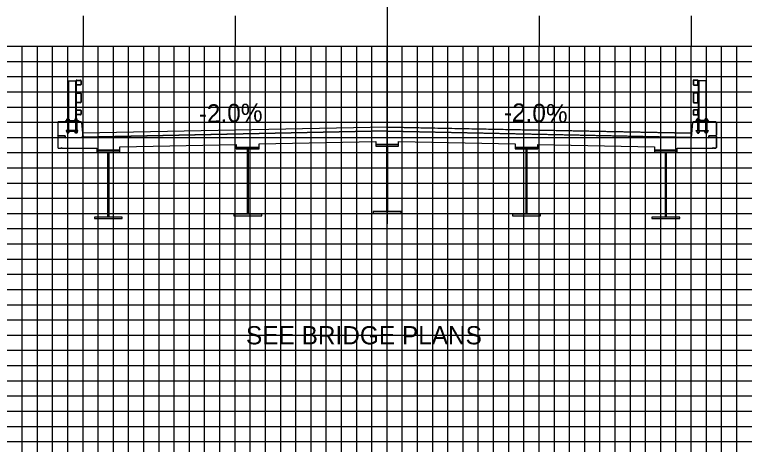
# Model space of a CAD drawing. Extents: x 1790124 to 1790467, y 442591 to 442811.
# Drawn here: x 1790265.2 to 1790313.2, y 442752.48 to 442780.74 of the extents above; entities that cross this region are included whole.
import ezdxf

# ---------------------------------------------------------------- set-up
doc = ezdxf.new("R2010")
doc.units = 0
for name, color, linetype in [('ANNOTATION', 7, 'Continuous'), ('BORDER', 7, 'Continuous'), ('D_Bridge_Framing', 7, 'Continuous'), ('D_Bridge_Railing', 7, 'Continuous'), ('D_Bridge_Superstructure', 7, 'Continuous'), ('DIMENSIONS', 7, 'Continuous'), ('MAJOR', 7, 'Continuous'), ('MINOR', 7, 'Continuous'), ('PATTERNING', 7, 'Continuous'), ('SHADING', 7, 'Continuous')]:
    doc.layers.add(name, color=color, linetype=linetype)

msp = doc.modelspace()

# ---------------------------------------------------------------- linework, layer by layer
at = {"layer": 'BORDER'}
for p, q in [((1790280.529, 442771.864), (1790280.529, 442770.826)), ((1790289.696, 442771.968), (1790289.696, 442770.93)), ((1790298.862, 442771.968), (1790298.862, 442770.93))]:
    msp.add_line(p, q, dxfattribs=at)
at = {"layer": 'D_Bridge_Framing'}
for points in [[(1790288.946, 442772.089), (1790290.446, 442772.089), (1790290.446, 442772.193), (1790288.946, 442772.193)], [(1790270.612, 442771.722), (1790272.112, 442771.722), (1790272.112, 442771.826), (1790270.612, 442771.826)], [(1790271.339, 442771.722), (1790271.386, 442771.722), (1790271.386, 442767.43), (1790271.339, 442767.43)], [(1790279.779, 442771.905), (1790281.279, 442771.905), (1790281.279, 442772.009), (1790279.779, 442772.009)], [(1790280.506, 442771.905), (1790280.553, 442771.905), (1790280.553, 442767.614), (1790280.506, 442767.614)], [(1790289.672, 442772.089), (1790289.719, 442772.089), (1790289.719, 442767.797), (1790289.672, 442767.797)], [(1790298.112, 442771.905), (1790299.612, 442771.905), (1790299.612, 442772.009), (1790298.112, 442772.009)], [(1790298.839, 442771.905), (1790298.886, 442771.905), (1790298.886, 442767.614), (1790298.839, 442767.614)], [(1790307.279, 442771.722), (1790308.779, 442771.722), (1790308.779, 442771.826), (1790307.279, 442771.826)], [(1790308.006, 442771.722), (1790308.053, 442771.722), (1790308.053, 442767.43), (1790308.006, 442767.43)], [(1790270.446, 442767.326), (1790272.279, 442767.326), (1790272.279, 442767.43), (1790270.446, 442767.43)], [(1790279.612, 442767.509), (1790281.446, 442767.509), (1790281.446, 442767.614), (1790279.612, 442767.614)], [(1790288.779, 442767.693), (1790290.612, 442767.693), (1790290.612, 442767.797), (1790288.779, 442767.797)], [(1790297.946, 442767.509), (1790299.779, 442767.509), (1790299.779, 442767.614), (1790297.946, 442767.614)], [(1790307.112, 442767.326), (1790308.946, 442767.326), (1790308.946, 442767.43), (1790307.112, 442767.43)]]:
    msp.add_lwpolyline(points, close=True, dxfattribs=at)
at = {"layer": 'D_Bridge_Railing'}
for p, q in [((1790268.706, 442776.395), (1790268.706, 442773.938)), ((1790268.706, 442776.395), (1790269.237, 442776.395)), ((1790268.743, 442776.395), (1790268.743, 442773.933)), ((1790269.201, 442776.395), (1790269.201, 442773.933)), ((1790269.237, 442776.145), (1790269.237, 442776.395)), ((1790269.237, 442776.395), (1790269.237, 442773.938)), ((1790269.258, 442776.145), (1790269.258, 442776.395)), ((1790269.279, 442776.437), (1790269.529, 442776.437)), ((1790269.279, 442776.416), (1790269.529, 442776.416)), ((1790269.529, 442776.124), (1790269.279, 442776.124)), ((1790269.529, 442776.104), (1790269.279, 442776.104)), ((1790269.55, 442776.395), (1790269.55, 442776.145)), ((1790269.571, 442776.395), (1790269.571, 442776.145)), ((1790309.821, 442776.395), (1790309.821, 442776.145)), ((1790309.842, 442776.395), (1790309.842, 442776.145)), ((1790310.113, 442776.437), (1790309.862, 442776.437)), ((1790310.113, 442776.416), (1790309.862, 442776.416)), ((1790309.862, 442776.124), (1790310.113, 442776.124)), ((1790309.862, 442776.104), (1790310.113, 442776.104)), ((1790310.133, 442776.145), (1790310.133, 442776.395)), ((1790310.154, 442776.145), (1790310.154, 442776.395)), ((1790310.154, 442776.395), (1790310.154, 442773.938)), ((1790310.685, 442776.395), (1790310.154, 442776.395)), ((1790310.191, 442776.395), (1790310.191, 442773.933)), ((1790310.649, 442776.395), (1790310.649, 442773.933)), ((1790310.685, 442776.395), (1790310.685, 442773.938)), ((1790269.237, 442774.989), (1790269.237, 442775.552)), ((1790269.263, 442774.989), (1790269.263, 442775.552)), ((1790269.289, 442775.604), (1790269.519, 442775.604)), ((1790269.289, 442775.578), (1790269.519, 442775.578)), ((1790269.545, 442775.552), (1790269.545, 442774.989)), ((1790269.571, 442775.552), (1790269.571, 442774.989)), ((1790309.821, 442775.552), (1790309.821, 442774.989)), ((1790309.847, 442775.552), (1790309.847, 442774.989)), ((1790310.102, 442775.604), (1790309.873, 442775.604)), ((1790310.102, 442775.578), (1790309.873, 442775.578)), ((1790310.128, 442774.989), (1790310.128, 442775.552)), ((1790310.154, 442774.989), (1790310.154, 442775.552)), ((1790269.519, 442774.963), (1790269.289, 442774.963)), ((1790269.519, 442774.937), (1790269.289, 442774.937)), ((1790309.873, 442774.963), (1790310.102, 442774.963)), ((1790309.873, 442774.937), (1790310.102, 442774.937)), ((1790269.237, 442774.187), (1790269.237, 442774.437)), ((1790269.258, 442774.187), (1790269.258, 442774.437)), ((1790269.279, 442774.479), (1790269.529, 442774.479)), ((1790269.279, 442774.458), (1790269.529, 442774.458)), ((1790269.529, 442774.166), (1790269.279, 442774.166)), ((1790269.529, 442774.145), (1790269.279, 442774.145)), ((1790269.55, 442774.437), (1790269.55, 442774.187)), ((1790269.571, 442774.437), (1790269.571, 442774.187)), ((1790309.821, 442774.437), (1790309.821, 442774.187)), ((1790309.842, 442774.437), (1790309.842, 442774.187)), ((1790310.113, 442774.479), (1790309.862, 442774.479)), ((1790310.113, 442774.458), (1790309.862, 442774.458)), ((1790309.862, 442774.166), (1790310.113, 442774.166)), ((1790309.862, 442774.145), (1790310.113, 442774.145)), ((1790310.133, 442774.187), (1790310.133, 442774.437)), ((1790310.154, 442774.187), (1790310.154, 442774.437)), ((1790268.665, 442773.928), (1790268.748, 442773.928)), ((1790268.665, 442773.866), (1790268.665, 442773.803)), ((1790268.665, 442773.687), (1790268.665, 442773.781)), ((1790268.706, 442773.938), (1790268.706, 442773.781)), ((1790268.747, 442773.866), (1790268.747, 442773.803)), ((1790268.748, 442773.687), (1790268.748, 442773.781)), ((1790269.279, 442773.928), (1790269.196, 442773.928)), ((1790269.196, 442773.866), (1790269.196, 442773.803)), ((1790269.196, 442773.687), (1790269.196, 442773.781)), ((1790269.238, 442773.938), (1790269.238, 442773.781)), ((1790269.279, 442773.866), (1790269.279, 442773.803)), ((1790269.279, 442773.687), (1790269.279, 442773.781)), ((1790310.112, 442773.928), (1790310.196, 442773.928)), ((1790310.112, 442773.687), (1790310.112, 442773.781)), ((1790310.113, 442773.866), (1790310.113, 442773.803)), ((1790310.154, 442773.938), (1790310.154, 442773.781)), ((1790310.195, 442773.866), (1790310.195, 442773.803)), ((1790310.196, 442773.687), (1790310.196, 442773.781)), ((1790310.727, 442773.928), (1790310.644, 442773.928)), ((1790310.644, 442773.866), (1790310.644, 442773.803)), ((1790310.644, 442773.687), (1790310.644, 442773.781)), ((1790310.685, 442773.938), (1790310.685, 442773.781)), ((1790310.726, 442773.866), (1790310.726, 442773.803)), ((1790310.727, 442773.687), (1790310.727, 442773.781)), ((1790268.665, 442773.117), (1790268.665, 442773.086)), ((1790268.748, 442773.117), (1790268.748, 442773.086)), ((1790269.196, 442773.117), (1790269.196, 442773.086)), ((1790269.279, 442773.117), (1790269.279, 442773.086)), ((1790310.112, 442773.117), (1790310.112, 442773.086)), ((1790310.196, 442773.117), (1790310.196, 442773.086)), ((1790310.644, 442773.117), (1790310.644, 442773.086)), ((1790310.727, 442773.117), (1790310.727, 442773.086))]:
    msp.add_line(p, q, dxfattribs=at)
for points in [[(1790268.555, 442773.781), (1790269.388, 442773.781), (1790269.388, 442773.697), (1790268.555, 442773.697)], [(1790268.555, 442773.697), (1790269.388, 442773.697), (1790269.388, 442773.687), (1790268.555, 442773.687)], [(1790268.619, 442773.781), (1790268.793, 442773.781), (1790268.793, 442773.794), (1790268.619, 442773.794)], [(1790268.624, 442773.866), (1790268.64, 442773.876), (1790268.772, 442773.876), (1790268.788, 442773.866), (1790268.788, 442773.803), (1790268.772, 442773.794), (1790268.64, 442773.794), (1790268.624, 442773.803)], [(1790269.324, 442773.781), (1790269.151, 442773.781), (1790269.151, 442773.794), (1790269.324, 442773.794)], [(1790269.32, 442773.866), (1790269.303, 442773.876), (1790269.171, 442773.876), (1790269.155, 442773.866), (1790269.155, 442773.803), (1790269.171, 442773.794), (1790269.303, 442773.794), (1790269.32, 442773.803)], [(1790310.836, 442773.781), (1790310.003, 442773.781), (1790310.003, 442773.697), (1790310.836, 442773.697)], [(1790310.836, 442773.697), (1790310.003, 442773.697), (1790310.003, 442773.687), (1790310.836, 442773.687)], [(1790310.067, 442773.781), (1790310.241, 442773.781), (1790310.241, 442773.794), (1790310.067, 442773.794)], [(1790310.072, 442773.866), (1790310.088, 442773.876), (1790310.22, 442773.876), (1790310.236, 442773.866), (1790310.236, 442773.803), (1790310.22, 442773.794), (1790310.088, 442773.794), (1790310.072, 442773.803)], [(1790310.772, 442773.781), (1790310.599, 442773.781), (1790310.599, 442773.794), (1790310.772, 442773.794)], [(1790310.768, 442773.866), (1790310.751, 442773.876), (1790310.619, 442773.876), (1790310.603, 442773.866), (1790310.603, 442773.803), (1790310.619, 442773.794), (1790310.751, 442773.794), (1790310.768, 442773.803)], [(1790269.362, 442773.117), (1790268.581, 442773.117), (1790268.581, 442773.086), (1790269.362, 442773.086)], [(1790310.029, 442773.117), (1790310.81, 442773.117), (1790310.81, 442773.086), (1790310.029, 442773.086)]]:
    msp.add_lwpolyline(points, close=True, dxfattribs=at)
for points in [[(1790268.665, 442773.876), (1790268.665, 442773.928), (1790268.675, 442773.938), (1790268.737, 442773.938), (1790268.748, 442773.928), (1790268.748, 442773.876)], [(1790268.665, 442773.687), (1790268.665, 442773.117)], [(1790268.748, 442773.687), (1790268.748, 442773.117)], [(1790269.279, 442773.876), (1790269.279, 442773.928), (1790269.269, 442773.938), (1790269.206, 442773.938), (1790269.196, 442773.928), (1790269.196, 442773.876)], [(1790269.196, 442773.687), (1790269.196, 442773.117)], [(1790269.279, 442773.687), (1790269.279, 442773.117)], [(1790310.112, 442773.876), (1790310.112, 442773.928), (1790310.123, 442773.938), (1790310.185, 442773.938), (1790310.196, 442773.928), (1790310.196, 442773.876)], [(1790310.112, 442773.687), (1790310.112, 442773.117)], [(1790310.196, 442773.687), (1790310.196, 442773.117)], [(1790310.727, 442773.876), (1790310.727, 442773.928), (1790310.717, 442773.938), (1790310.654, 442773.938), (1790310.644, 442773.928), (1790310.644, 442773.876)], [(1790310.644, 442773.687), (1790310.644, 442773.117)], [(1790310.727, 442773.687), (1790310.727, 442773.117)], [(1790268.793, 442773.086), (1790268.793, 442773.072), (1790268.619, 442773.072), (1790268.619, 442773.086)], [(1790268.64, 442773.072), (1790268.624, 442773.063), (1790268.624, 442773), (1790268.64, 442772.99), (1790268.772, 442772.99), (1790268.788, 442773), (1790268.788, 442773.063), (1790268.772, 442773.072)], [(1790268.665, 442772.99), (1790268.665, 442772.949), (1790268.675, 442772.938), (1790268.737, 442772.938), (1790268.748, 442772.949), (1790268.748, 442772.99)], [(1790269.151, 442773.086), (1790269.151, 442773.072), (1790269.324, 442773.072), (1790269.324, 442773.086)], [(1790269.303, 442773.072), (1790269.32, 442773.063), (1790269.32, 442773), (1790269.303, 442772.99), (1790269.171, 442772.99), (1790269.155, 442773), (1790269.155, 442773.063), (1790269.171, 442773.072)], [(1790269.279, 442772.99), (1790269.279, 442772.949), (1790269.269, 442772.938), (1790269.206, 442772.938), (1790269.196, 442772.949), (1790269.196, 442772.99)], [(1790310.241, 442773.086), (1790310.241, 442773.072), (1790310.067, 442773.072), (1790310.067, 442773.086)], [(1790310.088, 442773.072), (1790310.072, 442773.063), (1790310.072, 442773), (1790310.088, 442772.99), (1790310.22, 442772.99), (1790310.236, 442773), (1790310.236, 442773.063), (1790310.22, 442773.072)], [(1790310.112, 442772.99), (1790310.112, 442772.949), (1790310.123, 442772.938), (1790310.185, 442772.938), (1790310.196, 442772.949), (1790310.196, 442772.99)], [(1790310.599, 442773.086), (1790310.599, 442773.072), (1790310.772, 442773.072), (1790310.772, 442773.086)], [(1790310.751, 442773.072), (1790310.768, 442773.063), (1790310.768, 442773), (1790310.751, 442772.99), (1790310.619, 442772.99), (1790310.603, 442773), (1790310.603, 442773.063), (1790310.619, 442773.072)], [(1790310.727, 442772.99), (1790310.727, 442772.949), (1790310.717, 442772.938), (1790310.654, 442772.938), (1790310.644, 442772.949), (1790310.644, 442772.99)]]:
    msp.add_lwpolyline(points, dxfattribs=at)
for centre, radius, start, end in [((1790269.279, 442776.395), 0.0415, 90, 180), ((1790269.279, 442776.145), 0.0415, 180, 270), ((1790269.279, 442776.395), 0.0206, 90, 180), ((1790269.279, 442776.145), 0.0206, 180, 270), ((1790269.529, 442776.395), 0.0415, 0, 90), ((1790269.529, 442776.395), 0.0206, 0, 90), ((1790269.529, 442776.145), 0.0415, 270, 0), ((1790269.529, 442776.145), 0.0206, 270, 0), ((1790309.862, 442776.395), 0.0415, 90, 180), ((1790309.862, 442776.145), 0.0415, 180, 270), ((1790309.862, 442776.395), 0.0206, 90, 180), ((1790309.862, 442776.145), 0.0206, 180, 270), ((1790310.113, 442776.395), 0.0415, 0, 90), ((1790310.113, 442776.395), 0.0206, 0, 90), ((1790310.113, 442776.145), 0.0415, 270, 0), ((1790310.113, 442776.145), 0.0206, 270, 0), ((1790269.289, 442775.552), 0.0518, 90, 180), ((1790269.289, 442775.552), 0.0257, 90, 180), ((1790269.519, 442775.552), 0.0518, 360, 90), ((1790269.519, 442775.552), 0.0257, 360, 90), ((1790309.873, 442775.552), 0.0518, 90, 180), ((1790309.873, 442775.552), 0.0257, 90, 180), ((1790310.102, 442775.552), 0.0518, 0, 90), ((1790310.102, 442775.552), 0.0257, 0, 90), ((1790269.289, 442774.989), 0.0518, 180, 270), ((1790269.289, 442774.989), 0.0257, 180, 270), ((1790269.519, 442774.989), 0.0518, 270, 0), ((1790269.519, 442774.989), 0.0257, 270, 0), ((1790309.873, 442774.989), 0.0518, 180, 270), ((1790309.873, 442774.989), 0.0257, 180, 270), ((1790310.102, 442774.989), 0.0518, 270, 0), ((1790310.102, 442774.989), 0.0257, 270, 360), ((1790269.279, 442774.437), 0.0415, 90, 180), ((1790269.279, 442774.187), 0.0415, 180, 270), ((1790269.279, 442774.437), 0.0206, 90, 180), ((1790269.279, 442774.187), 0.0206, 180, 270), ((1790269.529, 442774.437), 0.0415, 0, 90), ((1790269.529, 442774.437), 0.0206, 0, 90), ((1790269.529, 442774.187), 0.0415, 270, 0), ((1790269.529, 442774.187), 0.0206, 270, 0), ((1790309.862, 442774.437), 0.0415, 90, 180), ((1790309.862, 442774.187), 0.0415, 180, 270), ((1790309.862, 442774.437), 0.0206, 90, 180), ((1790309.862, 442774.187), 0.0206, 180, 270), ((1790310.113, 442774.437), 0.0415, 0, 90), ((1790310.113, 442774.437), 0.0206, 0, 90), ((1790310.113, 442774.187), 0.0415, 270, 0), ((1790310.113, 442774.187), 0.0206, 270, 0), ((1790268.645, 442773.837), 0.036, 55.4339, 120), ((1790268.645, 442773.833), 0.036, 240, 304.5661), ((1790268.706, 442773.737), 0.136, 72.412, 107.588), ((1790268.706, 442773.933), 0.136, 252.412, 287.588), ((1790268.768, 442773.837), 0.036, 60, 124.5661), ((1790268.768, 442773.833), 0.036, 235.4339, 300), ((1790269.176, 442773.837), 0.036, 55.4339, 120), ((1790269.176, 442773.833), 0.036, 240, 304.5661), ((1790269.237, 442773.737), 0.136, 72.412, 107.588), ((1790269.237, 442773.933), 0.136, 252.412, 287.588), ((1790269.299, 442773.837), 0.036, 60, 124.5661), ((1790269.299, 442773.833), 0.036, 235.4339, 300), ((1790310.093, 442773.837), 0.036, 55.4339, 120), ((1790310.093, 442773.833), 0.036, 240, 304.5661), ((1790310.154, 442773.737), 0.136, 72.412, 107.588), ((1790310.154, 442773.933), 0.136, 252.412, 287.588), ((1790310.216, 442773.837), 0.036, 60, 124.5661), ((1790310.216, 442773.833), 0.036, 235.4339, 300), ((1790310.624, 442773.837), 0.036, 55.4339, 120), ((1790310.624, 442773.833), 0.036, 240, 304.5661), ((1790310.685, 442773.737), 0.136, 72.412, 107.588), ((1790310.685, 442773.933), 0.136, 252.412, 287.588), ((1790310.747, 442773.837), 0.036, 60, 124.5661), ((1790310.747, 442773.833), 0.036, 235.4339, 300)]:
    msp.add_arc(centre, radius, start, end, dxfattribs=at)
at = {"layer": 'D_Bridge_Superstructure'}
for p, q in [((1790268.029, 442773.645), (1790268.071, 442773.687)), ((1790268.029, 442773.645), (1790268.029, 442772.811)), ((1790269.571, 442773.687), (1790268.071, 442773.687)), ((1790269.616, 442773.645), (1790269.571, 442773.687)), ((1790269.616, 442773.645), (1790269.696, 442772.668)), ((1790309.776, 442773.645), (1790309.696, 442772.668)), ((1790309.776, 442773.645), (1790309.821, 442773.687)), ((1790309.821, 442773.687), (1790311.321, 442773.687)), ((1790311.362, 442773.645), (1790311.321, 442773.687)), ((1790311.362, 442773.645), (1790311.362, 442772.811)), ((1790289.696, 442773.339), (1790269.674, 442772.938)), ((1790289.696, 442773.339), (1790309.718, 442772.938)), ((1790268.071, 442772.769), (1790268.029, 442772.811)), ((1790268.529, 442772.769), (1790268.071, 442772.769)), ((1790268.529, 442772.769), (1790268.071, 442772.769)), ((1790289.696, 442773.068), (1790268.529, 442772.644)), ((1790268.529, 442772.769), (1790268.529, 442772.644)), ((1790268.529, 442772.644), (1790268.529, 442772.769)), ((1790289.696, 442773.089), (1790269.694, 442772.689)), ((1790289.696, 442773.089), (1790309.697, 442772.689)), ((1790289.696, 442773.068), (1790310.862, 442772.644)), ((1790309.696, 442772.668), (1790289.696, 442773.068)), ((1790310.862, 442772.644), (1790309.696, 442772.668)), ((1790310.862, 442772.769), (1790310.862, 442772.644)), ((1790310.862, 442772.769), (1790311.321, 442772.769)), ((1790311.321, 442772.769), (1790310.862, 442772.769)), ((1790310.862, 442772.769), (1790310.862, 442772.644)), ((1790311.321, 442772.769), (1790311.362, 442772.811)), ((1790288.946, 442772.193), (1790290.446, 442772.193)), ((1790268.237, 442771.968), (1790268.279, 442772.009)), ((1790268.279, 442772.009), (1790268.279, 442771.968)), ((1790270.612, 442771.826), (1790272.112, 442771.826)), ((1790279.779, 442772.009), (1790281.279, 442772.009)), ((1790298.112, 442772.009), (1790299.612, 442772.009)), ((1790307.279, 442771.826), (1790308.779, 442771.826)), ((1790311.112, 442771.968), (1790311.112, 442772.009)), ((1790311.112, 442772.009), (1790311.154, 442771.968))]:
    msp.add_line(p, q, dxfattribs=at)
for points in [[(1790268.071, 442772.769), (1790268.029, 442772.728), (1790268.029, 442772.009), (1790268.071, 442771.968), (1790268.237, 442771.968)], [(1790268.071, 442772.769), (1790268.029, 442772.728), (1790268.029, 442772.009), (1790268.071, 442771.968), (1790268.237, 442771.968)], [(1790289.696, 442773.068), (1790269.696, 442772.668), (1790268.529, 442772.644)], [(1790311.321, 442772.769), (1790311.362, 442772.728), (1790311.362, 442772.009), (1790311.321, 442771.968), (1790311.154, 442771.968)], [(1790311.154, 442771.968), (1790311.321, 442771.968), (1790311.362, 442772.009), (1790311.362, 442772.728), (1790311.321, 442772.769)], [(1790272.112, 442771.826), (1790272.112, 442772.049), (1790279.779, 442772.203), (1790279.779, 442772.009)], [(1790281.279, 442772.009), (1790281.279, 442772.233), (1790288.946, 442772.386), (1790288.946, 442772.193)], [(1790290.446, 442772.193), (1790290.446, 442772.386), (1790298.112, 442772.233), (1790298.112, 442772.009)], [(1790299.612, 442772.009), (1790299.612, 442772.203), (1790307.279, 442772.049), (1790307.279, 442771.826)], [(1790268.279, 442772.009), (1790268.237, 442771.968)], [(1790268.279, 442772.009), (1790268.279, 442771.968)], [(1790268.279, 442771.968), (1790270.612, 442771.968), (1790270.612, 442771.826)], [(1790308.779, 442771.826), (1790308.779, 442771.968), (1790311.112, 442771.968)], [(1790311.112, 442772.009), (1790311.112, 442771.968)], [(1790311.112, 442772.009), (1790311.154, 442771.968)]]:
    msp.add_lwpolyline(points, dxfattribs=at)
at = {"layer": 'DIMENSIONS'}
msp.add_line((1790289.696, 442782.187), (1790289.696, 442766.974), dxfattribs=at)
at = {"layer": 'MAJOR'}
for p, q in [((1790269.696, 442780.669), (1790269.696, 442778.665)), ((1790279.696, 442780.669), (1790279.696, 442778.665)), ((1790289.696, 442780.669), (1790289.696, 442778.665)), ((1790299.696, 442780.669), (1790299.696, 442778.665)), ((1790309.696, 442780.669), (1790309.696, 442778.665)), ((1790149.696, 442778.665), (1790429.696, 442778.665)), ((1790149.696, 442778.665), (1790429.696, 442778.665)), ((1790269.696, 442738.665), (1790269.696, 442778.665)), ((1790279.696, 442738.665), (1790279.696, 442778.665)), ((1790289.696, 442738.665), (1790289.696, 442778.665)), ((1790299.696, 442738.665), (1790299.696, 442778.665)), ((1790309.696, 442738.665), (1790309.696, 442778.665)), ((1790149.696, 442773.665), (1790429.696, 442773.665)), ((1790149.696, 442768.665), (1790429.696, 442768.665)), ((1790149.696, 442763.665), (1790429.696, 442763.665)), ((1790149.696, 442758.665), (1790429.696, 442758.665)), ((1790149.696, 442753.665), (1790429.696, 442753.665))]:
    msp.add_line(p, q, dxfattribs=at)
at = {"layer": 'MINOR'}
for p, q in [((1790265.696, 442738.665), (1790265.696, 442778.665)), ((1790266.696, 442738.665), (1790266.696, 442778.665)), ((1790267.696, 442738.665), (1790267.696, 442778.665)), ((1790268.696, 442738.665), (1790268.696, 442778.665)), ((1790270.696, 442738.665), (1790270.696, 442778.665)), ((1790271.696, 442738.665), (1790271.696, 442778.665)), ((1790272.696, 442738.665), (1790272.696, 442778.665)), ((1790273.696, 442738.665), (1790273.696, 442778.665)), ((1790274.696, 442738.665), (1790274.696, 442778.665)), ((1790275.696, 442738.665), (1790275.696, 442778.665)), ((1790276.696, 442738.665), (1790276.696, 442778.665)), ((1790277.696, 442738.665), (1790277.696, 442778.665)), ((1790278.696, 442738.665), (1790278.696, 442778.665)), ((1790280.696, 442738.665), (1790280.696, 442778.665)), ((1790281.696, 442738.665), (1790281.696, 442778.665)), ((1790282.696, 442738.665), (1790282.696, 442778.665)), ((1790283.696, 442738.665), (1790283.696, 442778.665)), ((1790284.696, 442738.665), (1790284.696, 442778.665)), ((1790285.696, 442738.665), (1790285.696, 442778.665)), ((1790286.696, 442738.665), (1790286.696, 442778.665)), ((1790287.696, 442738.665), (1790287.696, 442778.665)), ((1790288.696, 442738.665), (1790288.696, 442778.665)), ((1790290.696, 442738.665), (1790290.696, 442778.665)), ((1790291.696, 442738.665), (1790291.696, 442778.665)), ((1790292.696, 442738.665), (1790292.696, 442778.665)), ((1790293.696, 442738.665), (1790293.696, 442778.665)), ((1790294.696, 442738.665), (1790294.696, 442778.665)), ((1790295.696, 442738.665), (1790295.696, 442778.665)), ((1790296.696, 442738.665), (1790296.696, 442778.665)), ((1790297.696, 442738.665), (1790297.696, 442778.665)), ((1790298.696, 442738.665), (1790298.696, 442778.665)), ((1790300.696, 442738.665), (1790300.696, 442778.665)), ((1790301.696, 442738.665), (1790301.696, 442778.665)), ((1790302.696, 442738.665), (1790302.696, 442778.665)), ((1790303.696, 442738.665), (1790303.696, 442778.665)), ((1790304.696, 442738.665), (1790304.696, 442778.665)), ((1790305.696, 442738.665), (1790305.696, 442778.665)), ((1790306.696, 442738.665), (1790306.696, 442778.665)), ((1790307.696, 442738.665), (1790307.696, 442778.665)), ((1790308.696, 442738.665), (1790308.696, 442778.665)), ((1790310.696, 442738.665), (1790310.696, 442778.665)), ((1790311.696, 442738.665), (1790311.696, 442778.665)), ((1790312.696, 442738.665), (1790312.696, 442778.665)), ((1790149.696, 442777.665), (1790429.696, 442777.665)), ((1790149.696, 442776.665), (1790429.696, 442776.665)), ((1790149.696, 442775.665), (1790429.696, 442775.665)), ((1790149.696, 442774.665), (1790429.696, 442774.665)), ((1790149.696, 442772.665), (1790429.696, 442772.665)), ((1790149.696, 442771.665), (1790429.696, 442771.665)), ((1790149.696, 442770.665), (1790429.696, 442770.665)), ((1790149.696, 442769.665), (1790429.696, 442769.665)), ((1790149.696, 442767.665), (1790429.696, 442767.665)), ((1790149.696, 442766.665), (1790429.696, 442766.665)), ((1790149.696, 442765.665), (1790429.696, 442765.665)), ((1790149.696, 442764.665), (1790429.696, 442764.665)), ((1790149.696, 442762.665), (1790429.696, 442762.665)), ((1790149.696, 442761.665), (1790429.696, 442761.665)), ((1790149.696, 442760.665), (1790429.696, 442760.665)), ((1790149.696, 442759.665), (1790429.696, 442759.665)), ((1790149.696, 442757.665), (1790429.696, 442757.665)), ((1790149.696, 442756.665), (1790429.696, 442756.665)), ((1790149.696, 442755.665), (1790429.696, 442755.665)), ((1790149.696, 442754.665), (1790429.696, 442754.665)), ((1790149.696, 442752.665), (1790429.696, 442752.665))]:
    msp.add_line(p, q, dxfattribs=at)
at = {"layer": 'PATTERNING'}
for p, q in [((1790268.071, 442773.687), (1790268.029, 442773.645)), ((1790268.029, 442773.645), (1790268.029, 442772.811)), ((1790269.571, 442773.687), (1790268.071, 442773.687)), ((1790269.616, 442773.645), (1790269.571, 442773.687)), ((1790269.674, 442772.938), (1790269.616, 442773.645)), ((1790309.821, 442773.687), (1790309.776, 442773.645)), ((1790311.321, 442773.687), (1790309.821, 442773.687)), ((1790311.362, 442773.645), (1790311.321, 442773.687)), ((1790311.362, 442772.811), (1790311.362, 442773.645)), ((1790268.029, 442772.811), (1790268.071, 442772.769)), ((1790268.071, 442772.769), (1790268.529, 442772.769)), ((1790268.529, 442772.769), (1790268.529, 442772.644)), ((1790268.529, 442772.644), (1790269.696, 442772.668)), ((1790309.696, 442772.668), (1790310.862, 442772.644)), ((1790310.862, 442772.644), (1790310.862, 442772.769)), ((1790310.862, 442772.769), (1790311.321, 442772.769)), ((1790311.321, 442772.769), (1790311.362, 442772.811))]:
    msp.add_line(p, q, dxfattribs=at)
for points in [[(1790309.776, 442773.645), (1790309.718, 442772.938), (1790309.697, 442772.689), (1790309.696, 442772.668)], [(1790269.696, 442772.668), (1790269.694, 442772.689), (1790269.674, 442772.938)]]:
    msp.add_lwpolyline(points, dxfattribs=at)
at = {"layer": 'SHADING'}
for p, q in [((1790289.696, 442773.339), (1790269.674, 442772.938)), ((1790289.696, 442773.339), (1790269.674, 442772.938)), ((1790269.674, 442772.938), (1790269.694, 442772.689)), ((1790269.674, 442772.938), (1790269.694, 442772.689)), ((1790269.694, 442772.689), (1790289.696, 442773.089)), ((1790269.694, 442772.689), (1790289.696, 442773.089)), ((1790289.696, 442773.089), (1790309.697, 442772.689)), ((1790289.696, 442773.089), (1790309.697, 442772.689)), ((1790309.697, 442772.689), (1790309.718, 442772.938)), ((1790309.697, 442772.689), (1790309.718, 442772.938))]:
    msp.add_line(p, q, dxfattribs=at)
msp.add_lwpolyline([(1790309.718, 442772.938), (1790292.825, 442773.276), (1790289.696, 442773.339)], dxfattribs=at)
msp.add_lwpolyline([(1790309.718, 442772.938), (1790292.825, 442773.276), (1790289.696, 442773.339)], dxfattribs=at)

# ---------------------------------------------------------------- texts
at = {"layer": 'ANNOTATION'}
for rotation, p in [(1.1458, (1790277.32, 442773.625)), (358.8542, (1790297.364, 442773.719))]:
    msp.add_text('-2.0%', height=1.2, rotation=rotation, dxfattribs=at).set_placement(p)
msp.add_text('SEE BRIDGE PLANS', height=1.2, dxfattribs=at).set_placement((1790280.414, 442759.056))

doc.saveas('drawing.dxf')
